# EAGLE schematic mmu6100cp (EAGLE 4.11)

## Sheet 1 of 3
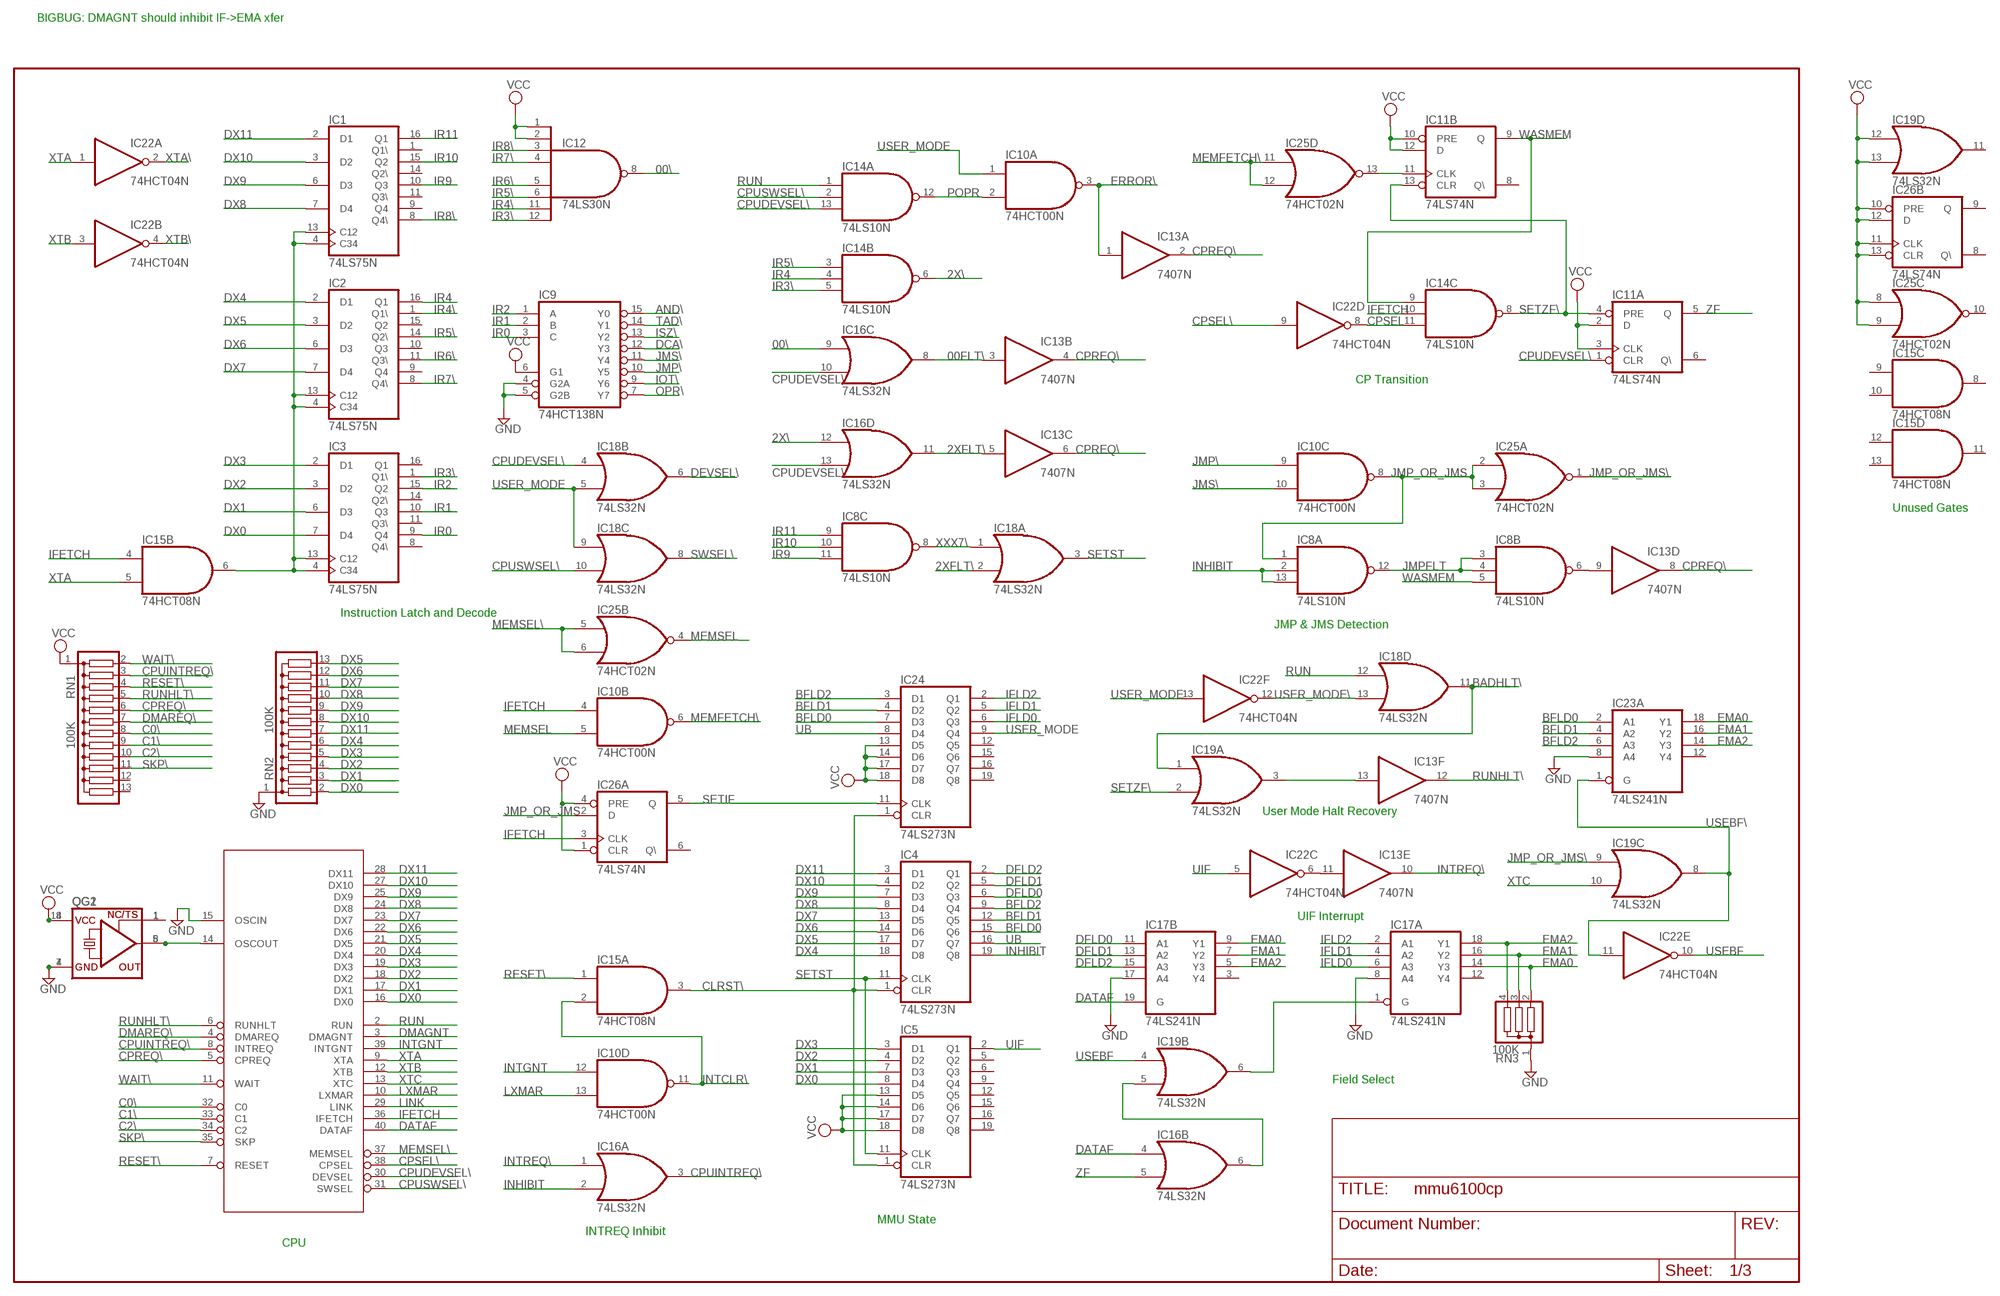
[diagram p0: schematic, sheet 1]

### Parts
CPU  IM6100  [DIL40]
IC1  74LS75N  [DIL16]
IC2  74LS75N  [DIL16]
IC3  74LS75N  [DIL16]
IC4  74LS273N  [DIL20]
IC5  74LS273N  [DIL20]
IC8  74LS10N  [DIL14]
IC9  74HCT138N  [DIL16]
IC10  74HCT00N  [DIL14]
IC11  74LS74N  [DIL14]
IC12  74LS30N  [DIL14]
IC13  7407N  [DIL14]
IC14  74LS10N  [DIL14]
IC15  74HCT08N  [DIL14]
IC16  74LS32N  [DIL14]
IC17  74LS241N  [DIL20]
IC18  74LS32N  [DIL14]
IC19  74LS32N  [DIL14]
IC22  74HCT04N  [DIL14]
IC23  74LS241N  [DIL20]
IC24  74LS273N  [DIL20]
IC25  74HCT02N  [DIL14]
IC26  74LS74N  [DIL14]
QG1  XO-8  [DIL08S]
QG2  XO-14  [DIL14S]
RN1  100K  G12R  [SIL13]
RN2  100K  G12R  [SIL13]
RN3  100K  G03R  [SIL4]

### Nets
00\: IC12.8(O) IC16.9(C:I0)
00FLT\: IC13.3(B:I) IC16.8(C:O)
2X\: IC14.6(B:O) IC16.12(D:I0)
2XFLT\: IC13.5(C:I) IC16.11(D:O) IC18.2(A:I1)
AND\: IC9.15(Y0) ; also sheet 3
BADHLT\: IC18.11(D:O) IC19.1(A:I0)
BFLD0: IC4.15(Q6) IC23.2(A:A1) IC24.7(D3)
BFLD1: IC4.12(Q5) IC23.4(A:A2) IC24.4(D2)
BFLD2: IC4.9(Q4) IC23.6(A:A3) IC24.3(D1)
C0\: CPU.32(C0) RN1.8 ; also sheet 3
C1\: CPU.33(C1) RN1.9 ; also sheet 3
C2\: CPU.34(C2) RN1.10 ; also sheet 3
CLRST\: IC4.1(CLR) IC5.1(CLR) IC15.3(A:O) IC24.1(CLR)
CPREQ\: CPU.5(CPREQ) IC13.2(A:O) IC13.4(B:O) IC13.6(C:O) IC13.8(D:O) RN1.6 ; also sheet 3
CPSEL: IC14.11(C:I2) IC22.8(D:O) ; also sheet 3
CPSEL\: CPU.38(CPSEL) IC22.9(D:I)
CPUDEVSEL\: CPU.30(DEVSEL) IC11.1(A:CLR) IC14.13(A:I2) IC16.10(C:I1) IC16.13(D:I1) IC18.4(B:I0)
CPUINTREQ\: CPU.8(INTREQ) IC16.3(A:O) RN1.3
CPUSWSEL\: CPU.31(SWSEL) IC14.2(A:I1) IC18.10(C:I1)
DATAF: CPU.40(DATAF) IC16.4(B:I0) IC17.19(B:G)
DCA\: IC9.12(Y3) ; also sheet 3
DEVSEL\: IC18.6(B:O) ; also sheet 3
DFLD0: IC4.6(Q3) IC17.11(B:A1)
DFLD1: IC4.5(Q2) IC17.13(B:A2)
DFLD2: IC4.2(Q1) IC17.15(B:A3)
DMAGNT: CPU.3(DMAGNT) ; also sheet 3
DMAREQ\: CPU.4(DMAREQ) RN1.7 ; also sheet 3
DX0: CPU.16(DX0) IC3.7(D4) IC5.8(D4) RN2.2 ; also sheet 3
DX1: CPU.17(DX1) IC3.6(D3) IC5.7(D3) RN2.3 ; also sheet 3
DX2: CPU.18(DX2) IC3.3(D2) IC5.4(D2) RN2.4 ; also sheet 3
DX3: CPU.19(DX3) IC3.2(D1) IC5.3(D1) RN2.5 ; also sheet 3
DX4: CPU.20(DX4) IC2.2(D1) IC4.18(D8) RN2.6 ; also sheet 3
DX5: CPU.21(DX5) IC2.3(D2) IC4.17(D7) RN2.13 ; also sheet 3
DX6: CPU.22(DX6) IC2.6(D3) IC4.14(D6) RN2.12 ; also sheet 3
DX7: CPU.23(DX7) IC2.7(D4) IC4.13(D5) RN2.11 ; also sheet 3
DX8: CPU.24(DX8) IC1.7(D4) IC4.8(D4) RN2.10 ; also sheet 3
DX9: CPU.25(DX9) IC1.6(D3) IC4.7(D3) RN2.9 ; also sheet 3
DX10: CPU.27(DX10) IC1.3(D2) IC4.4(D2) RN2.8 ; also sheet 3
DX11: CPU.28(DX11) IC1.2(D1) IC4.3(D1) RN2.7 ; also sheet 3
EMA0: IC17.9(B:Y1) IC17.14(A:Y3) IC23.18(A:Y1) RN3.2 ; also sheet 3
EMA1: IC17.7(B:Y2) IC17.16(A:Y2) IC23.16(A:Y2) RN3.3 ; also sheet 3
EMA2: IC17.5(B:Y3) IC17.18(A:Y1) IC23.14(A:Y3) RN3.4 ; also sheet 3
ERROR\: IC10.3(A:O) IC13.1(A:I)
GND: CPU.15(OSCIN) IC9.4(G2A) IC9.5(G2B) IC17.8(A:A4) IC17.17(B:A4) IC23.8(A:A4) QG1.4(GND) QG2.7(GND) RN2.1 RN3.1 ; also sheet 3
IFETCH: CPU.36(IFETCH) IC10.4(B:I0) IC14.10(C:I1) IC15.4(B:I0) IC26.3(A:CLK)
IFLD0: IC17.6(A:A3) IC24.6(Q3)
IFLD1: IC17.4(A:A2) IC24.5(Q2)
IFLD2: IC17.2(A:A1) IC24.2(Q1)
INHIBIT: IC4.19(Q8) IC8.2(A:I1) IC8.13(A:I2) IC16.2(A:I1)
INTCLR\: IC10.11(D:O) IC15.2(A:I1)
INTGNT: CPU.39(INTGNT) IC10.12(D:I0) ; also sheet 3
INTREQ\: IC13.10(E:O) IC16.1(A:I0) ; also sheet 3
IOT\: IC9.9(Y6) ; also sheet 3
IR0: IC3.9(Q4) IC9.3(C)
IR1: IC3.10(Q3) IC9.2(B)
IR2: IC3.15(Q2) IC9.1(A)
IR3\: IC3.1(Q1\) IC12.12(I7) IC14.5(B:I2)
IR4: IC2.16(Q1) IC14.4(B:I1)
IR4\: IC2.1(Q1\) IC12.11(I6)
IR5\: IC2.14(Q2\) IC12.6(I5) IC14.3(B:I0)
IR6\: IC2.11(Q3\) IC12.5(I4)
IR7\: IC2.8(Q4\) IC12.4(I3)
IR8\: IC1.8(Q4\) IC12.3(I2)
IR9: IC1.10(Q3) IC8.11(C:I2)
IR10: IC1.15(Q2) IC8.10(C:I1)
IR11: IC1.16(Q1) IC8.9(C:I0)
ISZ\: IC9.13(Y2) ; also sheet 3
JMP\: IC9.10(Y5) IC10.9(C:I0)
JMP_OR_JMS: IC8.1(A:I0) IC10.8(C:O) IC25.2(A:I0) IC25.3(A:I1) IC26.2(A:D)
JMP_OR_JMS\: IC19.9(C:I0) IC25.1(A:O)
JMPFLT: IC8.3(B:I0) IC8.4(B:I1) IC8.12(A:O)
JMS\: IC9.11(Y4) IC10.10(C:I1)
LINK: CPU.29(LINK) ; also sheet 3
LXMAR: CPU.10(LXMAR) IC10.13(D:I1) ; also sheet 3
MEMFETCH\: IC10.6(B:O) IC25.11(D:I0) IC25.12(D:I1)
MEMSEL: IC10.5(B:I1) IC25.4(B:O) ; also sheet 3
MEMSEL\: CPU.37(MEMSEL) IC25.5(B:I0) IC25.6(B:I1) ; also sheet 3
N$2: QG1.1(TS) QG2.1(TS)
N$3: IC1.4(C34) IC1.13(C12) IC2.4(C34) IC2.13(C12) IC3.4(C34) IC3.13(C12) IC15.6(B:O)
N$5: IC13.11(E:I) IC22.6(C:O)
N$6: IC11.11(B:CLK) IC25.13(D:O)
N$7: IC13.13(F:I) IC19.3(A:O)
N$8: IC16.6(B:O) IC19.5(B:I1)
N$10: IC17.1(A:G) IC19.6(B:O)
N$15: IC8.6(B:O) IC13.9(D:I)
OPR\: IC9.7(Y7) ; also sheet 3
OSCOUT: CPU.14(OSCOUT) QG1.5(OUT) QG2.8(OUT)
POPR: IC10.2(A:I1) IC14.12(A:O)
RESET\: CPU.7(RESET) IC15.1(A:I0) RN1.4 ; also sheet 3
RUN: CPU.2(RUN) IC14.1(A:I0) IC18.12(D:I0)
RUNHLT\: CPU.6(RUNHLT) IC13.12(F:O) RN1.5 ; also sheet 3
SETIF: IC24.11(CLK) IC26.5(A:Q)
SETST: IC4.11(CLK) IC5.11(CLK) IC18.3(A:O)
SETZF\: IC11.4(A:PRE) IC11.13(B:CLR) IC14.8(C:O) IC19.2(A:I1)
SKP\: CPU.35(SKP) RN1.11 ; also sheet 3
SWSEL\: IC18.8(C:O) ; also sheet 3
TAD\: IC9.14(Y1) ; also sheet 3
UB: IC4.16(Q7) IC24.8(D4)
UIF: IC5.2(Q1) IC22.5(C:I)
USEBF: IC19.4(B:I0) IC22.10(E:O)
USEBF\: IC19.8(C:O) IC22.11(E:I) IC23.1(A:G)
USER_MODE: IC10.1(A:I0) IC18.5(B:I1) IC18.9(C:I0) IC22.13(F:I) IC24.9(Q4)
USER_MODE\: IC18.13(D:I1) IC22.12(F:O)
VCC: IC5.13(D5) IC5.14(D6) IC5.17(D7) IC5.18(D8) IC9.6(G1) IC11.2(A:D) IC11.3(A:CLK) IC11.10(B:PRE) IC11.12(B:D) IC12.1(I0) IC12.2(I1) IC19.12(D:I0) IC19.13(D:I1) IC24.13(D5) IC24.14(D6) IC24.17(D7) IC24.18(D8) IC25.8(C:I0) IC25.9(C:I1) IC26.1(A:CLR) IC26.4(A:PRE) IC26.10(B:PRE) IC26.11(B:CLK) IC26.12(B:D) IC26.13(B:CLR) QG1.8(VCC) QG2.14(VCC) RN1.1 ; also sheet 3
WAIT\: CPU.11(WAIT) RN1.2 ; also sheet 3
WASMEM: IC8.5(B:I2) IC11.9(B:Q) IC14.9(C:I0)
XTA: CPU.9(XTA) IC15.5(B:I1) IC22.1(A:I) ; also sheet 3
XTA\: IC22.2(A:O)
XTB: CPU.12(XTB) IC22.3(B:I) ; also sheet 3
XTB\: IC22.4(B:O)
XTC: CPU.13(XTC) IC19.10(C:I1) ; also sheet 3
XXX7\: IC8.8(C:O) IC18.1(A:I0)
ZF: IC11.5(A:Q) IC16.5(B:I1)
Unconnected: IC1.1(Q1\) IC1.9(Q4) IC1.11(Q3\) IC1.14(Q2\) IC2.9(Q4) IC2.10(Q3) IC2.15(Q2) IC3.8(Q4\) IC3.11(Q3\) IC3.14(Q2\) IC3.16(Q1) IC5.5(Q2) IC5.6(Q3) IC5.9(Q4) IC5.12(Q5) IC5.15(Q6) IC5.16(Q7) IC5.19(Q8) IC11.6(A:Q\) IC11.8(B:Q\) IC15.8(C:O) IC15.9(C:I0) IC15.10(C:I1) IC15.11(D:O) IC15.12(D:I0) IC15.13(D:I1) IC17.3(B:Y4) IC17.12(A:Y4) IC19.11(D:O) IC23.3(B:Y4) IC23.5(B:Y3) IC23.7(B:Y2) IC23.9(B:Y1) IC23.11(B:A1) IC23.12(A:Y4) IC23.13(B:A2) IC23.15(B:A3) IC23.17(B:A4) IC23.19(B:G) IC24.12(Q5) IC24.15(Q6) IC24.16(Q7) IC24.19(Q8) IC25.10(C:O) IC26.6(A:Q\) IC26.8(B:Q\) IC26.9(B:Q) RN1.12 RN1.13

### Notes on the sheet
- BIGBUG: DMAGNT should inhibit IF->EMA xfer
- CP Transition
- Unused Gates
- Instruction Latch and Decode
- JMP & JMS Detection
- User Mode Halt Recovery
- UIF Interrupt
- Field Select
- MMU State
- INTREQ Inhibit
- CPU

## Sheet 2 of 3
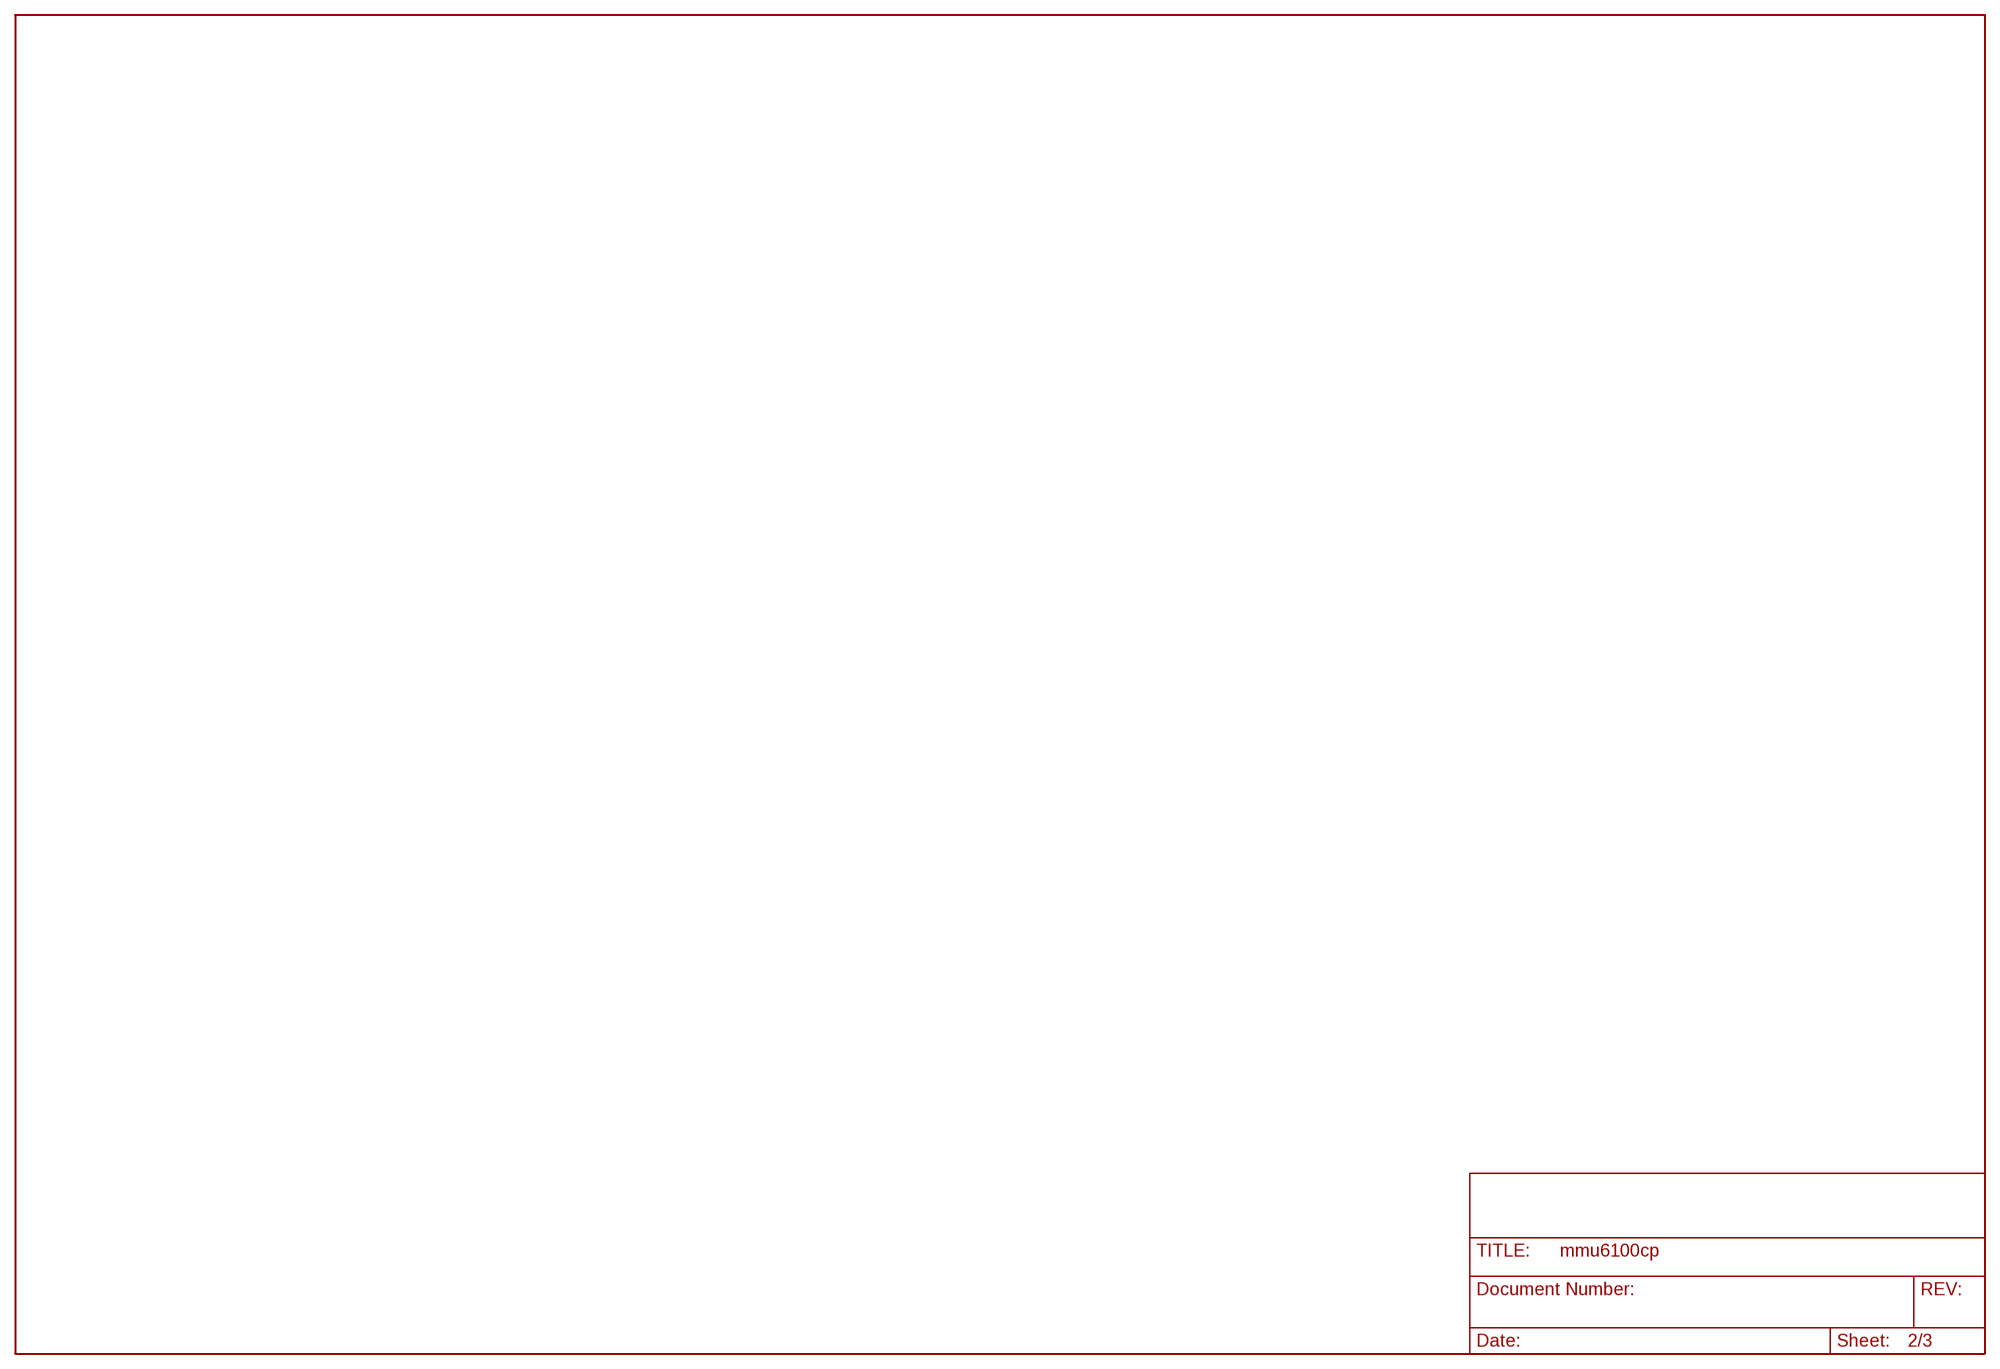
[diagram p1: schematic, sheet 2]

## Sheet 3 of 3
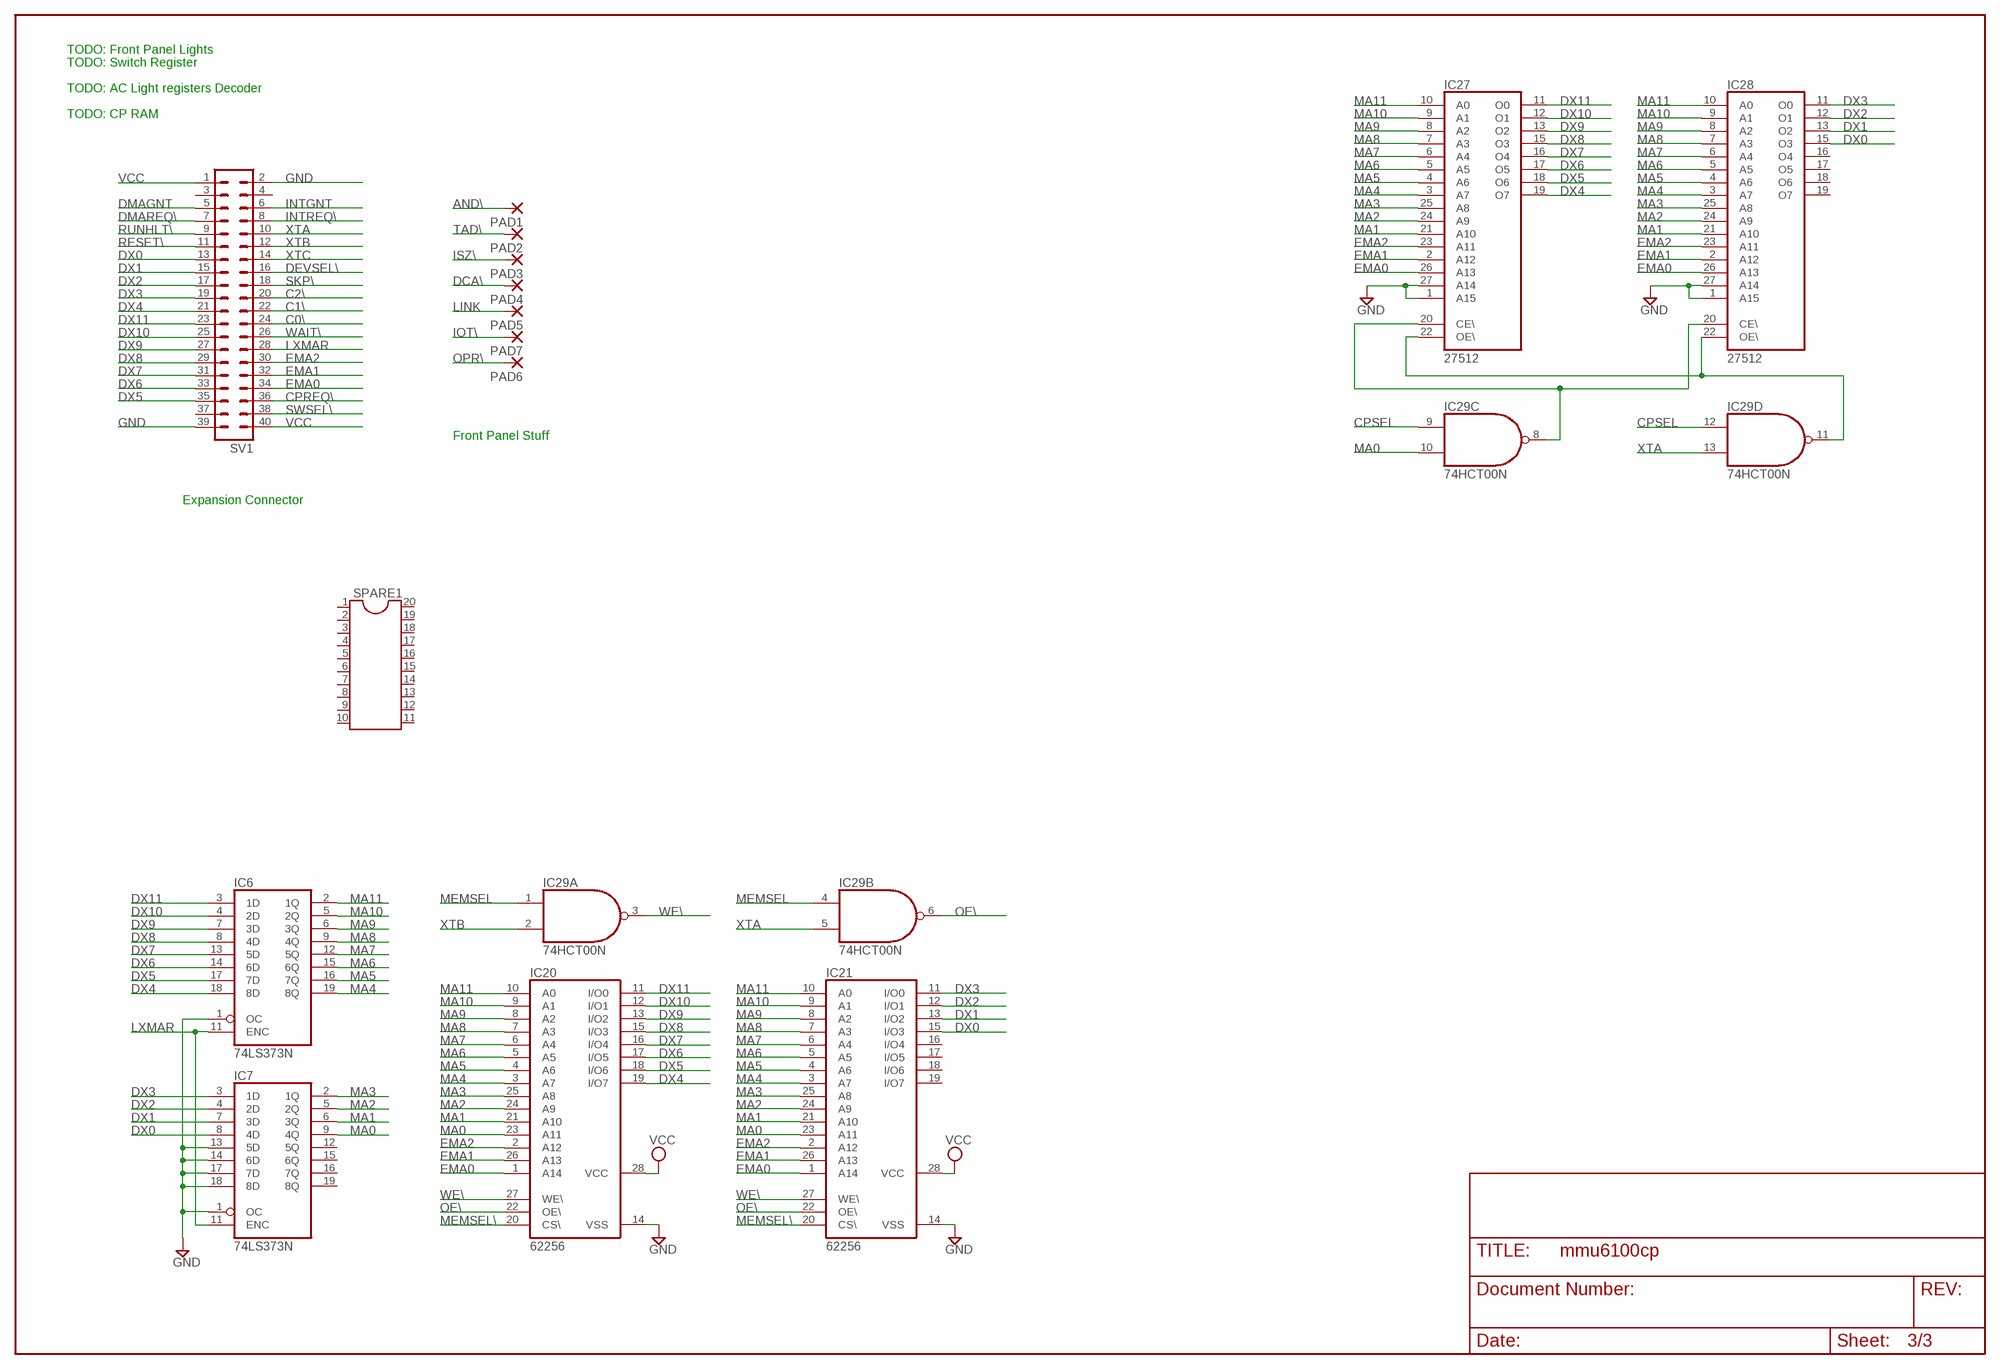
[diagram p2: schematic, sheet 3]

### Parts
IC6  74LS373N  [DIL20]
IC7  74LS373N  [DIL20]
IC20  62256  62256P  [DIL28-6]
IC21  62256  62256P  [DIL28-6]
IC27  27512  [DIL28]
IC28  27512  [DIL28]
IC29  74HCT00N  [DIL14]
PAD1  2,15/1,0  [2,15/1,0]
PAD2  2,15/1,0  [2,15/1,0]
PAD3  2,15/1,0  [2,15/1,0]
PAD4  2,15/1,0  [2,15/1,0]
PAD5  2,15/1,0  [2,15/1,0]
PAD6  2,15/1,0  [2,15/1,0]
PAD7  2,15/1,0  [2,15/1,0]
SPARE1  DIL20  [DIL20]
SV1  MA20-2  [MA20-2]

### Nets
AND\: PAD1.1(P) ; also sheet 1
C0\: SV1.24 ; also sheet 1
C1\: SV1.22 ; also sheet 1
C2\: SV1.20 ; also sheet 1
CPREQ\: SV1.36 ; also sheet 1
CPSEL: IC29.9(C:I0) IC29.12(D:I0) ; also sheet 1
DCA\: PAD4.1(P) ; also sheet 1
DEVSEL\: SV1.16 ; also sheet 1
DMAGNT: SV1.5 ; also sheet 1
DMAREQ\: SV1.7 ; also sheet 1
DX0: IC7.8(4D) IC21.15(I/O3) IC28.15(O3) SV1.13 ; also sheet 1
DX1: IC7.7(3D) IC21.13(I/O2) IC28.13(O2) SV1.15 ; also sheet 1
DX2: IC7.4(2D) IC21.12(I/O1) IC28.12(O1) SV1.17 ; also sheet 1
DX3: IC7.3(1D) IC21.11(I/O0) IC28.11(O0) SV1.19 ; also sheet 1
DX4: IC6.18(8D) IC20.19(I/O7) IC27.19(O7) SV1.21 ; also sheet 1
DX5: IC6.17(7D) IC20.18(I/O6) IC27.18(O6) SV1.35 ; also sheet 1
DX6: IC6.14(6D) IC20.17(I/O5) IC27.17(O5) SV1.33 ; also sheet 1
DX7: IC6.13(5D) IC20.16(I/O4) IC27.16(O4) SV1.31 ; also sheet 1
DX8: IC6.8(4D) IC20.15(I/O3) IC27.15(O3) SV1.29 ; also sheet 1
DX9: IC6.7(3D) IC20.13(I/O2) IC27.13(O2) SV1.27 ; also sheet 1
DX10: IC6.4(2D) IC20.12(I/O1) IC27.12(O1) SV1.25 ; also sheet 1
DX11: IC6.3(1D) IC20.11(I/O0) IC27.11(O0) SV1.23 ; also sheet 1
EMA0: IC20.1(A14) IC21.1(A14) IC27.26(A13) IC28.26(A13) SV1.34 ; also sheet 1
EMA1: IC20.26(A13) IC21.26(A13) IC27.2(A12) IC28.2(A12) SV1.32 ; also sheet 1
EMA2: IC20.2(A12) IC21.2(A12) IC27.23(A11) IC28.23(A11) SV1.30 ; also sheet 1
GND: IC6.1(OC) IC7.1(OC) IC7.13(5D) IC7.14(6D) IC7.17(7D) IC7.18(8D) IC20.14(VSS) IC21.14(VSS) IC27.1(A15) IC27.27(A14) IC28.1(A15) IC28.27(A14) SV1.2 SV1.39 ; also sheet 1
INTGNT: SV1.6 ; also sheet 1
INTREQ\: SV1.8 ; also sheet 1
IOT\: PAD7.1(P) ; also sheet 1
ISZ\: PAD3.1(P) ; also sheet 1
LINK: PAD5.1(P) ; also sheet 1
LXMAR: IC6.11(ENC) IC7.11(ENC) SV1.28 ; also sheet 1
MA0: IC7.9(4Q) IC20.23(A11) IC21.23(A11) IC29.10(C:I1)
MA1: IC7.6(3Q) IC20.21(A10) IC21.21(A10) IC27.21(A10) IC28.21(A10)
MA2: IC7.5(2Q) IC20.24(A9) IC21.24(A9) IC27.24(A9) IC28.24(A9)
MA3: IC7.2(1Q) IC20.25(A8) IC21.25(A8) IC27.25(A8) IC28.25(A8)
MA4: IC6.19(8Q) IC20.3(A7) IC21.3(A7) IC27.3(A7) IC28.3(A7)
MA5: IC6.16(7Q) IC20.4(A6) IC21.4(A6) IC27.4(A6) IC28.4(A6)
MA6: IC6.15(6Q) IC20.5(A5) IC21.5(A5) IC27.5(A5) IC28.5(A5)
MA7: IC6.12(5Q) IC20.6(A4) IC21.6(A4) IC27.6(A4) IC28.6(A4)
MA8: IC6.9(4Q) IC20.7(A3) IC21.7(A3) IC27.7(A3) IC28.7(A3)
MA9: IC6.6(3Q) IC20.8(A2) IC21.8(A2) IC27.8(A2) IC28.8(A2)
MA10: IC6.5(2Q) IC20.9(A1) IC21.9(A1) IC27.9(A1) IC28.9(A1)
MA11: IC6.2(1Q) IC20.10(A0) IC21.10(A0) IC27.10(A0) IC28.10(A0)
MEMSEL: IC29.1(A:I0) IC29.4(B:I0) ; also sheet 1
MEMSEL\: IC20.20(CS\) IC21.20(CS\) ; also sheet 1
N$9: IC27.20(CE\) IC28.20(CE\) IC29.8(C:O)
N$11: IC27.22(OE\) IC28.22(OE\) IC29.11(D:O)
OE\: IC20.22(OE\) IC21.22(OE\) IC29.6(B:O)
OPR\: PAD6.1(P) ; also sheet 1
RESET\: SV1.11 ; also sheet 1
RUNHLT\: SV1.9 ; also sheet 1
SKP\: SV1.18 ; also sheet 1
SWSEL\: SV1.38 ; also sheet 1
TAD\: PAD2.1(P) ; also sheet 1
VCC: IC20.28(VCC) IC21.28(VCC) SV1.1 SV1.40 ; also sheet 1
WAIT\: SV1.26 ; also sheet 1
WE\: IC20.27(WE\) IC21.27(WE\) IC29.3(A:O)
XTA: IC29.5(B:I1) IC29.13(D:I1) SV1.10 ; also sheet 1
XTB: IC29.2(A:I1) SV1.12 ; also sheet 1
XTC: SV1.14 ; also sheet 1
Unconnected: IC7.12(5Q) IC7.15(6Q) IC7.16(7Q) IC7.19(8Q) IC21.16(I/O4) IC21.17(I/O5) IC21.18(I/O6) IC21.19(I/O7) IC28.16(O4) IC28.17(O5) IC28.18(O6) IC28.19(O7) SPARE1.1 SPARE1.2 SPARE1.3 SPARE1.4 SPARE1.5 SPARE1.6 SPARE1.7 SPARE1.8 SPARE1.9 SPARE1.10 SPARE1.11 SPARE1.12 SPARE1.13 SPARE1.14 SPARE1.15 SPARE1.16 SPARE1.17 SPARE1.18 SPARE1.19 SPARE1.20 SV1.3 SV1.4 SV1.37

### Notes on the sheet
- TODO: Front Panel Lights
- TODO: Switch Register
- TODO: AC Light registers Decoder
- TODO: CP RAM
- Front Panel Stuff
- Expansion Connector

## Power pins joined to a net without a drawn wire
GND: CPU.26(GND) IC1.12(GND) IC2.12(GND) IC3.12(GND) IC4.10(GND) IC5.10(GND) IC6.10(GND) IC7.10(GND) IC8.7(P:GND) IC9.8(GND) IC10.7(P:GND) IC11.7(P:GND) IC12.7(GND) IC13.7(P:GND) IC14.7(P:GND) IC15.7(P:GND) IC16.7(P:GND) IC17.10(P:GND) IC18.7(P:GND) IC19.7(P:GND) IC22.7(P:GND) IC23.10(P:GND) IC24.10(GND) IC25.7(P:GND) IC26.7(P:GND) IC27.14(GND) IC28.14(GND) IC29.7(P:GND)
VCC: CPU.1(VCC) IC1.5(VCC) IC2.5(VCC) IC3.5(VCC) IC4.20(VCC) IC5.20(VCC) IC6.20(VCC) IC7.20(VCC) IC8.14(P:VCC) IC9.16(VCC) IC10.14(P:VCC) IC11.14(P:VCC) IC12.14(VCC) IC13.14(P:VCC) IC14.14(P:VCC) IC15.14(P:VCC) IC16.14(P:VCC) IC17.20(P:VCC) IC18.14(P:VCC) IC19.14(P:VCC) IC22.14(P:VCC) IC23.20(P:VCC) IC24.20(VCC) IC25.14(P:VCC) IC26.14(P:VCC) IC27.28(VCC) IC28.28(VCC) IC29.14(P:VCC)

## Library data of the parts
CPU = dec-con:IM6100: IM6100 PDP-8 on a chip.
IC1-IC3 = 74xx-jameco:74*75: 4-bit bistable LATCH
IC4 IC5 IC24 = 74xx-jameco:74*273: Octal D type FLIP FLOP, clear
IC6 IC7 = 74xx-jameco:74*373: Octal D type transparent LATCH
IC8 IC14 = 74xx-jameco:74*10: Triple 3-input NAND gate
IC9 = 74xx-jameco:74*138: 3-line to 8-line DECODER/DEMULTIPLEXER
IC10 IC29 = 74xx-jameco:74*00: Quad 2-input NAND gate
IC11 IC26 = 74xx-jameco:74*74: Dual D type positive edge triggered FLIP FLOP, preset and clear
IC12 = 74xx-jameco:74*30: 8-input NAND gate
IC13 = 74xx-jameco:74*07: Hex BUFFER, open collector high-voltage output
IC15 = 74xx-jameco:74*08: Quad 2-input AND gate
IC16 IC18 IC19 = 74xx-jameco:74*32: Quad 2-input OR gate
IC17 IC23 = 74xx-jameco:74*241: Octal BUFFER and LINE DRIVER, 3-state
IC20 IC21 = memory-hitachi:62256P: MEMORY
IC22 = 74xx-jameco:74*04: Hex INVERTER
IC25 = 74xx-jameco:74*02: Quad 2-input NOR gate
IC27 IC28 = memory:27512: MEMORY
PAD1-PAD7 = wirepad:2,15/1,0: THROUGH-HOLE PAD
QG1 QG2 = crystal:XO-: CRYSTAL
RN1 RN2 = resistor-sil:G12R: SIL RESISTOR
RN3 = resistor-sil:G03R: SIL RESISTOR
SPARE1 = ic-package:DIL20: Dual In Line
SV1 = con-lstb:MA20-2: PIN HEADER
